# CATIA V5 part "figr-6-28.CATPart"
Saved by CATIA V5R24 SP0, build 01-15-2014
Part number: Part1
Bounding box of the stored display mesh (mm): x -150 to 0, y -70 to 60, z -20 to 40
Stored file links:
  D:\KAVITA\CATIA V5-6R2014 Project_ Kavita\CATIA V5-6R2014_partfiles\Partfiles\c06_catia_v5-6r2014_prt\figr-6-28.CATPart
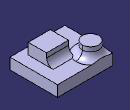
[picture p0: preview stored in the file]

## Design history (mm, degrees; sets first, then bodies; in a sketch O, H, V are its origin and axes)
Body1 (main body)
  Sketch1 on yz-plane, origin (0, 0, 0), H (0, 1, 0), V (0, 0, 1)
    line L1 (-70, 10) -> (60, 10)
    line L2 (60, 10) -> (60, -20)
    line L3 (60, -20) -> (-70, -20)
    line L4 (-70, -20) -> (-70, 10)
    horizontal: L1 H, L3 H
    vertical: L2 V, L4 V
  Pad1: profile Sketch1, direction (-1, 0, 0), length 150
  Sketch2 on face of Pad1 from Sketch1.L1, origin (0, 0, 10), H (1, 0, 0), V (0, 1, 0)
    circle A1 centre (-120, 30) radius 22.3607
  Pad2: profile Sketch2, direction (0, 0, 1), length 30
  Sketch3 on face of Pad1 from Sketch1.L1, origin (0, 0, 10), H (1, 0, 0), V (0, 1, 0)
    point P1 (-90, 0)
    line L1 (-90, 0) -> (-30, 0)
    line L2 (-30, 0) -> (-30, -50)
    line L3 (-30, -50) -> (-90, -50)
    line L4 (-90, -50) -> (-90, 0)
    coincidence: P1 H
    horizontal: L1 H, L3 H
    vertical: L2 V, L4 V
  Pad3: profile Sketch3, direction (0, 0, 1), length 30
  Fillet1: radius 18, on edge [face of Pad1 from Sketch1.L1 | face of Pad3 from Sketch3.L1]; edge [face of Pad1 from Sketch1.L1 | face of Pad2 from Sketch2.A1]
